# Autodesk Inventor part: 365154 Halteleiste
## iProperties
Company: Mayer & Müller AG Schaltgeräte
Created: 2006-07
Part Number: 365154 Halteleiste
Document SubType Name: Sheet Metal
Designer: I.Baliuc
Material: 1.0120.01
Description: Halteleiste
Density: 7.84 g/cm^3
Sheet Metal Rule: Default
HalbzeugNorm: DIN 174
Zweck: Vorkontakt HSLT
Abmessung: Fl.St. 25x5
Author: T.Messerschmitt
Keywords: 380156
Revision Number: 365154
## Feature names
1. Bohrung2 [Hole]
2. Bohrung3 [Hole]
3. Grobblech1
4. Biegung1
5. ExtrusionAbwicklung2
